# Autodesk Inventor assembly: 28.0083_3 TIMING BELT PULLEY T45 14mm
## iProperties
Created: 2006-12
Part Number: 28.0083_3 TIMING BELT PULLEY T45 14mm
Document SubType Name: Assembly
Designer: Andy Moles
Author: Andy Moles
